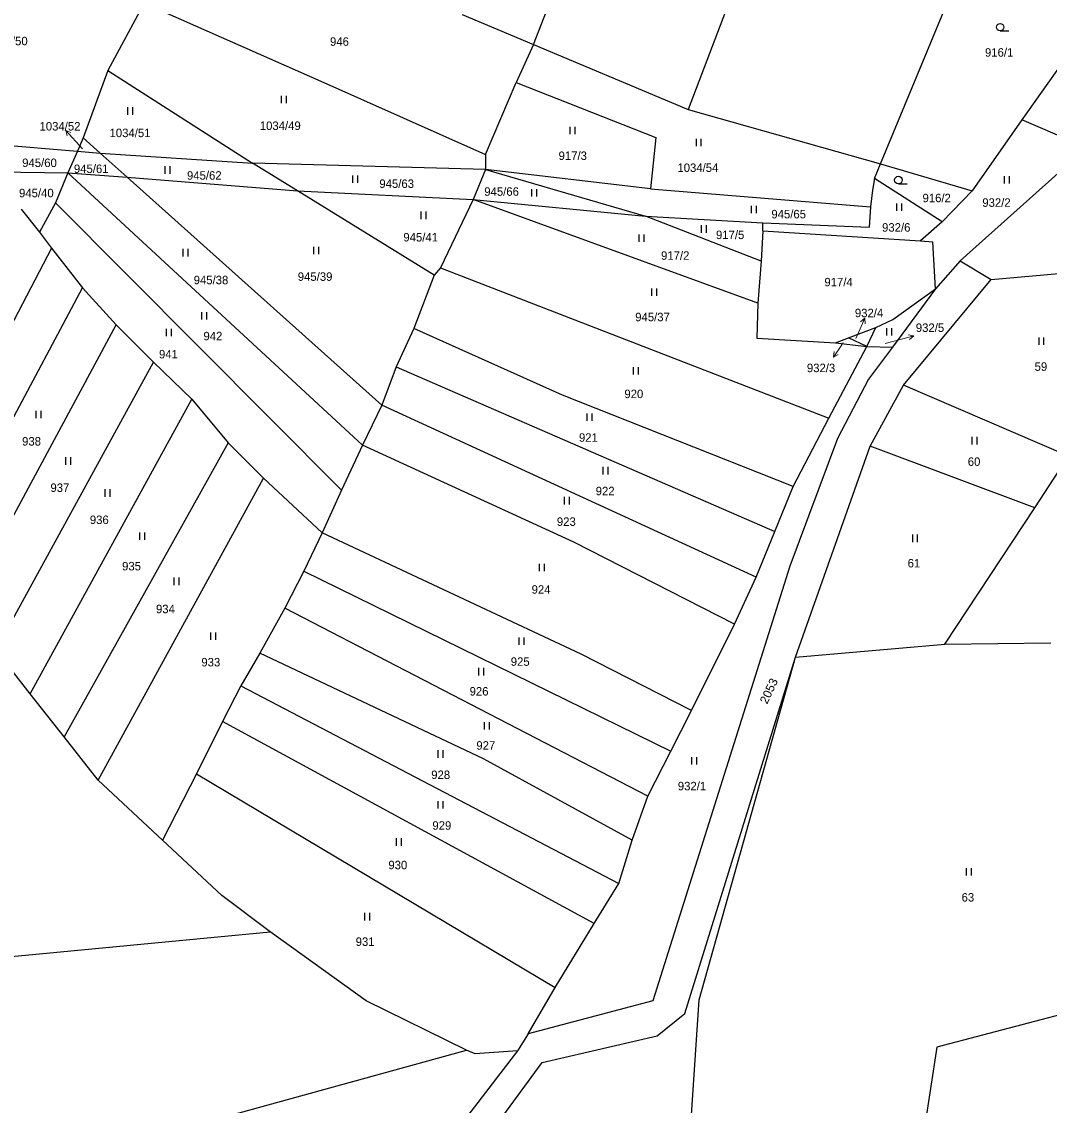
# Model space of a CAD drawing. Extents: x -820420 to -815896, y -1105820 to -1103643.
# Drawn here: x -818020.2 to -817814, y -1104919.6 to -1104702.1 of the extents above; entities that cross this region are included whole.
import ezdxf
from ezdxf.enums import TextEntityAlignment as Align

# ---------------------------------------------------------------- set-up
doc = ezdxf.new("R2010")
doc.units = 0
doc.header["$LTSCALE"] = 0.68
for name, color, linetype, lineweight in [('1', 7, 'Continuous', 25), ('3', 7, 'Continuous', 25), ('7', 7, 'Continuous', 13)]:
    doc.layers.add(name, color=color, linetype=linetype, lineweight=lineweight)
doc.layers.add('2', color=7, linetype='Continuous')

msp = doc.modelspace()

# ---------------------------------------------------------------- linework, layer by layer
at = {"layer": '1'}
for p, q in [((-817917.49, -1104706.69), (-817879.6, -1104609.1)), ((-817858.82, -1104647.39), (-817886.45, -1104719.72)), ((-817847.86, -1104730.64), (-817823.09, -1104670.81)), ((-817995.58, -1104698.35), (-818002.92, -1104711.85)), ((-817995.58, -1104698.35), (-817960.13, -1104714.02)), ((-817931.76, -1104700.67), (-817917.49, -1104706.69)), ((-817806.14, -1104702.92), (-817819.49, -1104721.8)), ((-817917.49, -1104706.69), (-817920.93, -1104714.27)), ((-817917.49, -1104706.69), (-817886.45, -1104719.72)), ((-818002.92, -1104711.85), (-818007.84, -1104725.42)), ((-818002.92, -1104711.85), (-817973.88, -1104730.45)), ((-817960.13, -1104714.02), (-817927.13, -1104728.71)), ((-817927.13, -1104728.71), (-817920.93, -1104714.27)), ((-817920.93, -1104714.27), (-817892.9, -1104725.32)), ((-817886.45, -1104719.72), (-817847.86, -1104730.64)), ((-817819.49, -1104721.8), (-817829.42, -1104736.02)), ((-817806.46, -1104727.35), (-817819.49, -1104721.8)), ((-818007.84, -1104725.42), (-818009, -1104728.09)), ((-818007.84, -1104725.42), (-818004.43, -1104728.47)), ((-817892.9, -1104725.32), (-817893.98, -1104735.64)), ((-818031.98, -1104726.15), (-818009, -1104728.09)), ((-818009, -1104728.09), (-818010.89, -1104732.44)), ((-818009, -1104728.09), (-818004.43, -1104728.47)), ((-817806.46, -1104727.35), (-817831.84, -1104750.1)), ((-818004.43, -1104728.47), (-817973.88, -1104730.45)), ((-818004.43, -1104728.47), (-817999.04, -1104733.3)), ((-817927.13, -1104728.71), (-817927.09, -1104731.73)), ((-818026.31, -1104732.17), (-818010.89, -1104732.44)), ((-818010.89, -1104732.44), (-818013.37, -1104738.43)), ((-817951.81, -1104787.07), (-818010.89, -1104732.44)), ((-818010.89, -1104732.44), (-817999.04, -1104733.3)), ((-817927.09, -1104731.73), (-817973.88, -1104730.45)), ((-817964.85, -1104736.02), (-817973.88, -1104730.45)), ((-817927.09, -1104731.73), (-817929.59, -1104737.79)), ((-817927.09, -1104731.73), (-817894.98, -1104741.09)), ((-817893.98, -1104735.64), (-817927.09, -1104731.73)), ((-817849.08, -1104733.59), (-817847.86, -1104730.64)), ((-817847.86, -1104730.64), (-817829.42, -1104736.02)), ((-817999.04, -1104733.3), (-817947.91, -1104779.02)), ((-817999.04, -1104733.3), (-817964.85, -1104736.02)), ((-817849.08, -1104733.59), (-817849.48, -1104735.88)), ((-817835.45, -1104742.23), (-817849.08, -1104733.59)), ((-817937.39, -1104752.98), (-817964.85, -1104736.02)), ((-817964.85, -1104736.02), (-817929.59, -1104737.79)), ((-817893.98, -1104735.64), (-817849.88, -1104739.26)), ((-817849.48, -1104735.88), (-817849.88, -1104739.26)), ((-817829.42, -1104736.02), (-817835.45, -1104742.23)), ((-818013.37, -1104738.43), (-818016.62, -1104744.33)), ((-818013.37, -1104738.43), (-817956.03, -1104796.12)), ((-817929.59, -1104737.79), (-817936.12, -1104751.49)), ((-817929.59, -1104737.79), (-817894.98, -1104741.09)), ((-817872.46, -1104758.59), (-817929.59, -1104737.79)), ((-818020.27, -1104739.71), (-818016.62, -1104744.33)), ((-817871.81, -1104750.12), (-817894.98, -1104741.09)), ((-817894.98, -1104741.09), (-817871.44, -1104742.46)), ((-817849.88, -1104739.26), (-817850.13, -1104743.34)), ((-817871.44, -1104744.09), (-817871.44, -1104742.46)), ((-817871.44, -1104742.46), (-817850.13, -1104743.34)), ((-817835.45, -1104742.23), (-817839.81, -1104746.05)), ((-818016.62, -1104744.33), (-818014.17, -1104747.56)), ((-817871.44, -1104744.09), (-817871.81, -1104750.12)), ((-817871.44, -1104744.09), (-817839.81, -1104746.05)), ((-818014.17, -1104747.56), (-818044.68, -1104805.85)), ((-818014.17, -1104747.56), (-818008, -1104755.48)), ((-817839.81, -1104746.05), (-817837.36, -1104746.24)), ((-817836.78, -1104755.71), (-817837.36, -1104746.24)), ((-817936.12, -1104751.49), (-817937.39, -1104752.98)), ((-817936.12, -1104751.49), (-817858.22, -1104781.63)), ((-817871.81, -1104750.12), (-817872.46, -1104758.59)), ((-817831.84, -1104750.1), (-817825.65, -1104753.8)), ((-817937.39, -1104752.98), (-817941.49, -1104763.69)), ((-817843.22, -1104775.07), (-817825.65, -1104753.8)), ((-817825.65, -1104753.8), (-817806.06, -1104752.09)), ((-818038.09, -1104812.01), (-818008, -1104755.48)), ((-818008, -1104755.48), (-818001.24, -1104762.92)), ((-817845.34, -1104761.83), (-817836.78, -1104755.71)), ((-817872.46, -1104758.59), (-817872.69, -1104765.6)), ((-818031.68, -1104819.54), (-818001.24, -1104762.92)), ((-818001.24, -1104762.92), (-817993.71, -1104770.43)), ((-817848.81, -1104763.49), (-817845.34, -1104761.83)), ((-817941.49, -1104763.69), (-817945, -1104771.39)), ((-817911.68, -1104777.06), (-817941.49, -1104763.69)), ((-817854.24, -1104765.56), (-817848.81, -1104763.49)), ((-817850.58, -1104767.3), (-817848.81, -1104763.49)), ((-817872.69, -1104765.6), (-817856.9, -1104766.57)), ((-817856.9, -1104766.57), (-817854.24, -1104765.56)), ((-817856.9, -1104766.57), (-817850.58, -1104767.3)), ((-817850.58, -1104767.3), (-817854.24, -1104765.56)), ((-817858.22, -1104781.63), (-817850.58, -1104767.3)), ((-817850.58, -1104767.3), (-817845.47, -1104767.42)), ((-817845.47, -1104767.42), (-817850.25, -1104773.84)), ((-818025.35, -1104828.16), (-817993.71, -1104770.43)), ((-817993.71, -1104770.43), (-817986.01, -1104777.87)), ((-817945, -1104771.39), (-817947.91, -1104779.02)), ((-817945, -1104771.39), (-817869.05, -1104804.42)), ((-817850.25, -1104773.84), (-817856.47, -1104785.74)), ((-817849.89, -1104787.31), (-817843.22, -1104775.07)), ((-817810.13, -1104789.27), (-817843.22, -1104775.07)), ((-818018.44, -1104836.96), (-817986.01, -1104777.87)), ((-817986.01, -1104777.87), (-817978.75, -1104786.59)), ((-817865.4, -1104795.37), (-817911.68, -1104777.06)), ((-817947.91, -1104779.02), (-817951.81, -1104787.07)), ((-817872.77, -1104813.55), (-817947.91, -1104779.02)), ((-817865.4, -1104795.37), (-817858.22, -1104781.63)), ((-817978.75, -1104786.59), (-818011.65, -1104845.62)), ((-817978.75, -1104786.59), (-817971.65, -1104793.69)), ((-817856.47, -1104785.74), (-817866.01, -1104811.37)), ((-817951.81, -1104787.07), (-817956.03, -1104796.12)), ((-817909.38, -1104806.52), (-817951.81, -1104787.07)), ((-817864.9, -1104829.63), (-817849.89, -1104787.31)), ((-817816.86, -1104799.64), (-817849.89, -1104787.31)), ((-817816.86, -1104799.64), (-817810.13, -1104789.27)), ((-818004.82, -1104854.3), (-817971.65, -1104793.69)), ((-817971.65, -1104793.69), (-817959.88, -1104804.67)), ((-817869.05, -1104804.42), (-817865.4, -1104795.37)), ((-817956.03, -1104796.12), (-817959.88, -1104804.67)), ((-817834.95, -1104827.02), (-817816.86, -1104799.64)), ((-817959.88, -1104804.67), (-817963.53, -1104812.36)), ((-817907.94, -1104829.01), (-817959.88, -1104804.67)), ((-817872.77, -1104813.55), (-817869.05, -1104804.42)), ((-817877.15, -1104823.02), (-817909.38, -1104806.52)), ((-817963.53, -1104812.36), (-817967.37, -1104819.78)), ((-817963.53, -1104812.36), (-817889.94, -1104848.51)), ((-817866.01, -1104811.37), (-817893.53, -1104898.6)), ((-817877.15, -1104823.02), (-817872.77, -1104813.55)), ((-817967.37, -1104819.78), (-817972.39, -1104828.8)), ((-817894.52, -1104857.5), (-817967.37, -1104819.78)), ((-817885.76, -1104840.31), (-817877.15, -1104823.02)), ((-818018.44, -1104836.96), (-818025.35, -1104828.16)), ((-817864.9, -1104829.63), (-817834.95, -1104827.02)), ((-817834.95, -1104827.02), (-817813.66, -1104826.75)), ((-817972.39, -1104828.8), (-817976.21, -1104835.35)), ((-817927.49, -1104850.04), (-817972.39, -1104828.8)), ((-817885.76, -1104840.31), (-817907.94, -1104829.01)), ((-817887.1, -1104901.16), (-817864.9, -1104829.63)), ((-817884.23, -1104898.39), (-817864.9, -1104829.63)), ((-817976.21, -1104835.35), (-817979.85, -1104842.57)), ((-817976.21, -1104835.35), (-817900.38, -1104875.06)), ((-818011.65, -1104845.62), (-818018.44, -1104836.96)), ((-817889.94, -1104848.51), (-817885.76, -1104840.31)), ((-817979.85, -1104842.57), (-817985.08, -1104853.04)), ((-817905.27, -1104883.08), (-817979.85, -1104842.57)), ((-818004.82, -1104854.3), (-818011.65, -1104845.62)), ((-817894.52, -1104857.5), (-817889.94, -1104848.51)), ((-817897.65, -1104866.35), (-817927.49, -1104850.04)), ((-817985.08, -1104853.04), (-817991.92, -1104866.34)), ((-817985.08, -1104853.04), (-817913.11, -1104895.96)), ((-817991.92, -1104866.34), (-818004.82, -1104854.3)), ((-817897.65, -1104866.35), (-817894.52, -1104857.5)), ((-817980.04, -1104877.45), (-817991.92, -1104866.34)), ((-817900.38, -1104875.06), (-817897.65, -1104866.35)), ((-817970.33, -1104884.79), (-817980.04, -1104877.45)), ((-818162.12, -1104902.94), (-817970.33, -1104884.79)), ((-817951.02, -1104898.64), (-817970.33, -1104884.79)), ((-817772.69, -1104891.13), (-817836.56, -1104907.89)), ((-817918.55, -1104905.23), (-817913.11, -1104895.96)), ((-817930.9, -1104908.48), (-817951.02, -1104898.64)), ((-817893.53, -1104898.6), (-817918.55, -1104905.23)), ((-817886.64, -1104933.91), (-817884.23, -1104898.39)), ((-817892.66, -1104905.66), (-817887.1, -1104901.16)), ((-817918.55, -1104905.23), (-817920.67, -1104908.63)), ((-817915.74, -1104911), (-817892.66, -1104905.66)), ((-818020.08, -1104933.05), (-817930.9, -1104908.48)), ((-817920.67, -1104908.63), (-817943.64, -1104938.51)), ((-817929.18, -1104909.23), (-817930.9, -1104908.48)), ((-817920.67, -1104908.63), (-817929.18, -1104909.23)), ((-817836.56, -1104907.89), (-817847.04, -1104977.28)), ((-817928.58, -1104928.45), (-817915.74, -1104911))]:
    msp.add_line(p, q, dxfattribs=at)
for points in [[(-817831.84, -1104750.1), (-817836.78, -1104755.71), (-817845.47, -1104767.42)], [(-817913.11, -1104895.96), (-817905.27, -1104883.08), (-817900.38, -1104875.06)]]:
    msp.add_lwpolyline(points, dxfattribs=at)
at = {"layer": '3'}
for p, q in [((-817823.843, -1104703.93), (-817822.093, -1104703.93)), ((-817968.011, -1104718.44), (-817968.011, -1104716.94)), ((-817967.01, -1104718.44), (-817967.01, -1104716.94)), ((-817998.841, -1104720.76), (-817998.841, -1104719.26)), ((-817997.84, -1104720.76), (-817997.84, -1104719.26)), ((-817910.111, -1104724.66), (-817910.111, -1104723.16)), ((-817909.11, -1104724.66), (-817909.11, -1104723.16)), ((-817884.801, -1104727.07), (-817884.801, -1104725.57)), ((-817883.8, -1104727.07), (-817883.8, -1104725.57)), ((-817991.411, -1104732.59), (-817991.411, -1104731.09)), ((-817990.41, -1104732.59), (-817990.41, -1104731.09)), ((-817953.701, -1104734.45), (-817953.701, -1104732.95)), ((-817952.7, -1104734.45), (-817952.7, -1104732.95)), ((-817844.263, -1104734.62), (-817842.513, -1104734.62)), ((-817822.971, -1104734.58), (-817822.971, -1104733.08)), ((-817821.97, -1104734.58), (-817821.97, -1104733.08)), ((-817917.831, -1104737.18), (-817917.831, -1104735.68)), ((-817916.83, -1104737.18), (-817916.83, -1104735.68)), ((-817844.551, -1104740.05), (-817844.551, -1104738.55)), ((-817843.55, -1104740.05), (-817843.55, -1104738.55)), ((-817940.011, -1104741.69), (-817940.011, -1104740.19)), ((-817939.01, -1104741.69), (-817939.01, -1104740.19)), ((-817873.711, -1104740.53), (-817873.711, -1104739.03)), ((-817872.71, -1104740.53), (-817872.71, -1104739.03)), ((-817883.761, -1104744.44), (-817883.761, -1104742.94)), ((-817882.76, -1104744.44), (-817882.76, -1104742.94)), ((-817896.281, -1104746.28), (-817896.281, -1104744.78)), ((-817895.28, -1104746.28), (-817895.28, -1104744.78)), ((-817987.751, -1104749.19), (-817987.751, -1104747.69)), ((-817986.75, -1104749.19), (-817986.75, -1104747.69)), ((-817961.541, -1104748.76), (-817961.541, -1104747.26)), ((-817960.54, -1104748.76), (-817960.54, -1104747.26)), ((-817893.761, -1104757.14), (-817893.761, -1104755.64)), ((-817892.76, -1104757.14), (-817892.76, -1104755.64)), ((-817984.001, -1104761.86), (-817984.001, -1104760.36)), ((-817983, -1104761.86), (-817983, -1104760.36)), ((-817991.111, -1104765.23), (-817991.111, -1104763.73)), ((-817990.11, -1104765.23), (-817990.11, -1104763.73)), ((-817846.591, -1104765.07), (-817846.591, -1104763.57)), ((-817845.59, -1104765.07), (-817845.59, -1104763.57)), ((-817816.041, -1104766.95), (-817816.041, -1104765.45)), ((-817815.04, -1104766.95), (-817815.04, -1104765.45)), ((-817897.401, -1104772.91), (-817897.401, -1104771.41)), ((-817896.4, -1104772.91), (-817896.4, -1104771.41)), ((-818017.291, -1104781.69), (-818017.291, -1104780.19)), ((-818016.29, -1104781.69), (-818016.29, -1104780.19)), ((-817906.711, -1104782.22), (-817906.711, -1104780.72)), ((-817905.71, -1104782.22), (-817905.71, -1104780.72)), ((-817829.451, -1104786.93), (-817829.451, -1104785.43)), ((-817828.45, -1104786.93), (-817828.45, -1104785.43)), ((-818011.341, -1104791), (-818011.341, -1104789.5)), ((-818010.34, -1104791), (-818010.34, -1104789.5)), ((-817903.481, -1104792.96), (-817903.481, -1104791.46)), ((-817902.48, -1104792.96), (-817902.48, -1104791.46)), ((-818003.421, -1104797.43), (-818003.421, -1104795.93)), ((-818002.42, -1104797.43), (-818002.42, -1104795.93)), ((-817911.271, -1104798.97), (-817911.271, -1104797.47)), ((-817910.27, -1104798.97), (-817910.27, -1104797.47)), ((-817996.441, -1104806.1), (-817996.441, -1104804.6)), ((-817995.44, -1104806.1), (-817995.44, -1104804.6)), ((-817841.391, -1104806.54), (-817841.391, -1104805.04)), ((-817840.39, -1104806.54), (-817840.39, -1104805.04)), ((-817916.241, -1104812.39), (-817916.241, -1104810.89)), ((-817915.24, -1104812.39), (-817915.24, -1104810.89)), ((-817989.591, -1104815.15), (-817989.591, -1104813.65)), ((-817988.59, -1104815.15), (-817988.59, -1104813.65)), ((-817982.221, -1104826.15), (-817982.221, -1104824.65)), ((-817981.22, -1104826.15), (-817981.22, -1104824.65)), ((-817920.321, -1104827.17), (-817920.321, -1104825.67)), ((-817919.32, -1104827.17), (-817919.32, -1104825.67)), ((-817928.461, -1104833.28), (-817928.461, -1104831.78)), ((-817927.46, -1104833.28), (-817927.46, -1104831.78)), ((-817927.331, -1104844.15), (-817927.331, -1104842.65)), ((-817926.33, -1104844.15), (-817926.33, -1104842.65)), ((-817936.611, -1104849.81), (-817936.611, -1104848.31)), ((-817935.61, -1104849.81), (-817935.61, -1104848.31)), ((-817885.731, -1104851.17), (-817885.731, -1104849.67)), ((-817884.73, -1104851.17), (-817884.73, -1104849.67)), ((-817936.611, -1104860), (-817936.611, -1104858.5)), ((-817935.61, -1104860), (-817935.61, -1104858.5)), ((-817944.981, -1104867.47), (-817944.981, -1104865.97)), ((-817943.98, -1104867.47), (-817943.98, -1104865.97)), ((-817830.601, -1104873.45), (-817830.601, -1104871.95)), ((-817829.6, -1104873.45), (-817829.6, -1104871.95)), ((-817951.321, -1104882.47), (-817951.321, -1104880.97)), ((-817950.32, -1104882.47), (-817950.32, -1104880.97))]:
    msp.add_line(p, q, dxfattribs=at)
for centre in [(-817823.8429, -1104703.1798), (-817844.2629, -1104733.8698)]:
    msp.add_circle(centre, 0.75, dxfattribs=at)
at = {"layer": '7'}
for p, q in [((-818011.328, -1104723.92), (-818011.03, -1104724.999)), ((-817850.979, -1104761.588), (-817851.844, -1104762.3)), ((-817841.191, -1104765.133), (-817842.288, -1104764.909)), ((-817857.308, -1104769.408), (-817856.333, -1104768.858))]:
    msp.add_line(p, q, dxfattribs=at)
for points in [[(-818007.99, -1104727.63), (-818009.32, -1104726.15), (-818011.328, -1104723.92), (-818010.286, -1104724.329)], [(-817852.79, -1104765.64), (-817852.2, -1104764.33), (-817850.979, -1104761.588), (-817850.929, -1104762.707)], [(-817855.34, -1104766.49), (-817855.63, -1104766.92), (-817857.308, -1104769.408), (-817857.163, -1104768.298)], [(-817846.93, -1104766.66), (-817844.09, -1104765.91), (-817841.191, -1104765.133), (-817842.029, -1104765.876)]]:
    msp.add_lwpolyline(points, dxfattribs=at)

# ---------------------------------------------------------------- texts
at = {"layer": '2'}
for s, p in [('1034/50', (-818023.079, -1104706.815)), ('946', (-817956.409, -1104706.925)), ('916/1', (-817824.04, -1104709.105)), ('1034/51', (-817998.439, -1104725.255)), ('1034/49', (-817968.289, -1104723.815)), ('917/3', (-817909.6, -1104729.835)), ('945/60', (-818016.6, -1104731.255)), ('945/61', (-818006.22, -1104732.455)), ('945/62', (-817983.53, -1104733.795)), ('1034/54', (-817884.489, -1104732.245)), ('945/63', (-817944.93, -1104735.445)), ('945/40', (-818017.23, -1104737.325)), ('945/66', (-817923.88, -1104737.025)), ('916/2', (-817836.57, -1104738.325)), ('932/2', (-817824.58, -1104739.235)), ('945/65', (-817866.27, -1104741.555)), ('932/6', (-817844.69, -1104744.225)), ('945/41', (-817940.11, -1104746.195)), ('917/5', (-817878.02, -1104745.715)), ('917/2', (-817889.04, -1104749.875)), ('945/38', (-817982.19, -1104754.785)), ('945/39', (-817961.3, -1104754.095)), ('917/4', (-817856.26, -1104755.195)), ('945/37', (-817893.59, -1104762.205)), ('942', (-817981.809, -1104766.035)), ('941', (-817990.729, -1104769.665)), ('59', (-817815.659, -1104772.155)), ('920', (-817897.339, -1104777.635)), ('921', (-817906.459, -1104786.395)), ('938', (-818018.199, -1104787.155)), ('60', (-817829.069, -1104791.235)), ('937', (-818012.509, -1104796.465)), ('922', (-817903.099, -1104797.135)), ('936', (-818004.599, -1104802.905)), ('923', (-817910.889, -1104803.275)), ('935', (-817998.129, -1104812.215)), ('61', (-817841.139, -1104811.625)), ('924', (-817915.959, -1104816.895)), ('934', (-817991.329, -1104820.805)), ('933', (-817982.229, -1104831.485)), ('925', (-817920.139, -1104831.365)), ('926', (-817928.399, -1104837.335)), ('927', (-817927.049, -1104848.195)), ('928', (-817936.099, -1104854.085)), ('932/1', (-817885.67, -1104856.355)), ('929', (-817935.869, -1104864.265)), ('930', (-817944.699, -1104872.195)), ('63', (-817830.309, -1104878.685)), ('931', (-817951.259, -1104887.585))]:
    msp.add_text(s, height=1.7, dxfattribs=at).set_placement(p, align=Align.CENTER)
for s, p in [('1034/52', (-818008.38, -1104723.925)), ('932/3', (-817856.93, -1104772.425))]:
    msp.add_text(s, height=1.7, dxfattribs=at).set_placement(p, align=Align.RIGHT)
for s, p in [('932/4', (-817852.99, -1104761.395)), ('932/5', (-817840.76, -1104764.355))]:
    msp.add_text(s, height=1.7, dxfattribs=at).set_placement(p)
at = {"layer": '2', "width": 1.05}
msp.add_text('2053', height=1.7, rotation=65, dxfattribs=at).set_placement((-817869.479, -1104836.7757), align=Align.CENTER)

doc.saveas('drawing.dxf')
